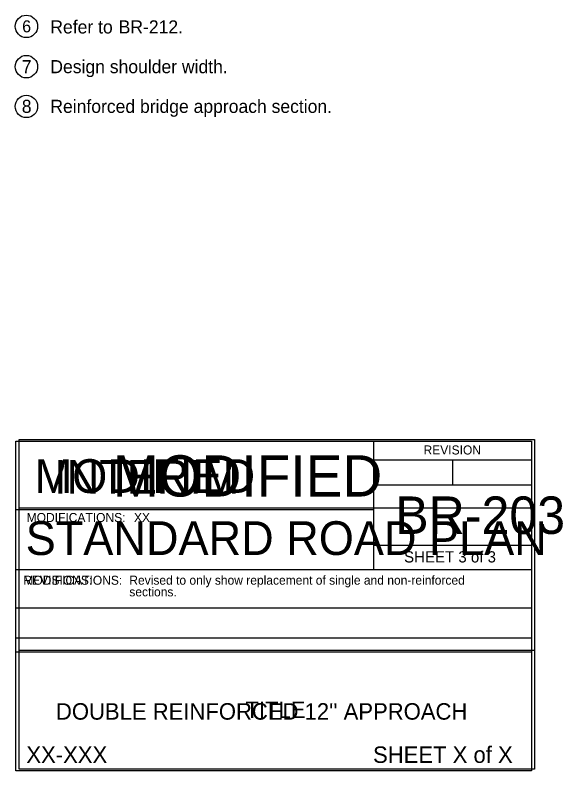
# Model space of a CAD drawing. Extents: x -2134860 to -2124557, y -2139046 to -2137324.
# Drawn here: x -2125289 to -2124557, y -2139046 to -2138038 of the extents above; entities that cross this region are included whole.
import ezdxf

# ---------------------------------------------------------------- set-up
doc = ezdxf.new("R2010")
doc.units = 0
for name, color, linetype in [('Barrier', 7, 'Continuous'), ('BridgeSuperStructureExisting', 7, 'Continuous'), ('Dimension', 7, 'Continuous'), ('dsnAlignmentCurveData', 7, 'Continuous'), ('dsnAlignmentTic', 7, 'Continuous'), ('DsnShtInsideBorder', 7, 'Continuous'), ('DsnShtPlotIdentification', 7, 'Continuous')]:
    doc.layers.add(name, color=color, linetype=linetype)

msp = doc.modelspace()

# ---------------------------------------------------------------- linework, layer by layer
at = {"layer": 'BridgeSuperStructureExisting'}
for centre in [(-2125273.5, -2138052.6), (-2125273.5, -2138106.4), (-2125273.5, -2138159.4)]:
    msp.add_circle(centre, 15, dxfattribs=at)
at = {"layer": 'Dimension'}
for p, q in [((-2124810.4, -2138605.9), (-2124810.4, -2138697.3)), ((-2124810.4, -2138630.9), (-2124599.4, -2138630.9)), ((-2124704.9, -2138630.9), (-2124704.9, -2138664.1)), ((-2124810.4, -2138664.1), (-2124599.4, -2138664.1)), ((-2125287.5, -2138697.3), (-2124810.4, -2138697.3)), ((-2124810.4, -2138697.3), (-2124810.4, -2138777.3)), ((-2124599.4, -2138745.1), (-2124810.4, -2138745.1)), ((-2125287.5, -2138777.3), (-2124599.4, -2138777.3)), ((-2125287.5, -2138828.3), (-2124599.4, -2138828.3)), ((-2125287.5, -2138868.3), (-2124599.4, -2138868.3)), ((-2125287.5, -2138887.3), (-2124599.4, -2138887.3))]:
    msp.add_line(p, q, dxfattribs=at)
msp.add_lwpolyline([(-2125287.5, -2138605.9), (-2124599.4, -2138605.9), (-2124599.4, -2139045.9), (-2125287.5, -2139045.9)], close=True, dxfattribs=at)
msp.add_lwpolyline([(-2125287.5, -2138605.9), (-2124599.4, -2138605.9), (-2124599.4, -2139045.9), (-2125287.5, -2139045.9)], close=True, dxfattribs=at)
at = {"layer": 'DsnShtInsideBorder'}
for p, q in [((-2125283.1, -2138695), (-2124595.1, -2138695)), ((-2125283.1, -2138885), (-2124595.1, -2138885))]:
    msp.add_line(p, q, dxfattribs=at)
msp.add_lwpolyline([(-2125283.1, -2138603.7), (-2124595.1, -2138603.7), (-2124595.1, -2139043.7), (-2125283.1, -2139043.7)], close=True, dxfattribs=at)

# ---------------------------------------------------------------- texts
at = {"layer": 'Barrier'}
for s, height, p in [('6', 16, (-2125279.1, -2138060.6)), ('Refer to ', 17.5, (-2125241.5, -2138062.1)), ('BR-212.', 17.5, (-2125150.3, -2138062.1)), ('7', 17.5, (-2125279.5, -2138115.1)), ('Design shoulder width.', 17.5, (-2125241.5, -2138115.1)), ('8', 17.5, (-2125279.6, -2138168.1)), ('Reinforced bridge approach section.', 17.5, (-2125241.5, -2138168.1))]:
    msp.add_text(s, height=height, dxfattribs=at).set_placement(p)
at = {"layer": 'Dimension'}
for s, height, p in [('REVISION', 12, (-2124743.4, -2138623.8)), ('BR-203', 50, (-2124781.2, -2138729.8)), ('STANDARD ROAD PLAN', 45.001, (-2125274.4, -2138757.9)), ('SHEET 3 of 3', 15, (-2124769.4, -2138767.9)), ('Revised to only show replacement of single and non-reinforced', 12, (-2125136.1, -2138797.5)), ('sections.', 12, (-2125136.1, -2138813.1)), ("DOUBLE REINFORCED 12'' APPROACH", 22, (-2125234, -2138977.6))]:
    msp.add_text(s, height=height, dxfattribs=at).set_placement(p)
at = {"layer": 'dsnAlignmentCurveData'}
msp.add_text('REVISIONS:', height=12, dxfattribs=at).set_placement((-2125277.5, -2138797.6))
at = {"layer": 'dsnAlignmentTic'}
for s, height, p in [('MODIFIED', 45, (-2125262.4, -2138675.1)), ('MODIFICATIONS:', 12, (-2125277.5, -2138797.6))]:
    msp.add_text(s, height=height, dxfattribs=at).set_placement(p)
at = {"layer": 'DsnShtInsideBorder'}
for s, height, p in [('MODIFIED', 55, (-2125158.1, -2138679.9)), ('MODIFICATIONS:', 12, (-2125273.1, -2138713.9)), ('XX', 12, (-2125129.9, -2138713.9)), ('TITLE', 22, (-2124981.1, -2138975.4)), ('XX-XXX', 22, (-2125273.5, -2139035.3)), ('SHEET X of X', 22, (-2124810.8, -2139035.3))]:
    msp.add_text(s, height=height, dxfattribs=at).set_placement(p)
at = {"layer": 'DsnShtPlotIdentification'}
msp.add_text('INTERIM', height=45, dxfattribs=at).set_placement((-2125236.5, -2138676.3))

doc.saveas('drawing.dxf')
